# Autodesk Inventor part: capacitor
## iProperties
Created: 2009-10
Part Number: capacitor
Document SubType Name: Modeling
Designer: Pika
Density: 1 g/cm^3
Author: Pika
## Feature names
1. Extrusion1
